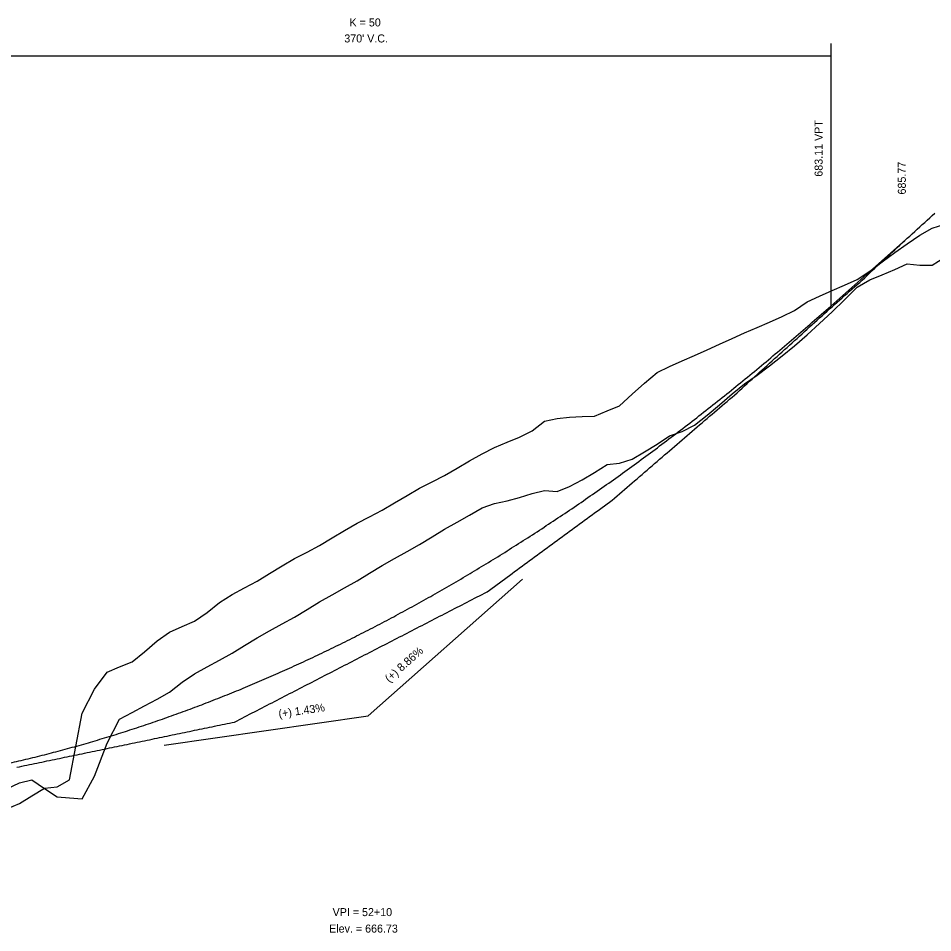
# Model space of a CAD drawing. Extents: x 1733584 to 1737559, y 1214897 to 1219897.
# Drawn here: x 1735549.8 to 1735915.5, y 1217977.4 to 1218342.9 of the extents above; entities that cross this region are included whole.
import ezdxf

# ---------------------------------------------------------------- set-up
doc = ezdxf.new("R2010")
doc.units = 0
for name, color, linetype in [('RD_DDB_GradeTX', 7, 'Continuous'), ('RD_DDB_Profile_EX', 7, 'Continuous'), ('RD_DDB_Profile_Lbl', 7, 'Continuous'), ('RD_DDB_Profile_PR', 7, 'Continuous'), ('RD_DDB_StripGrade', 7, 'Continuous'), ('RD_DDB_VCLbl', 7, 'Continuous'), ('RD_Sketch1', 7, 'Continuous'), ('RD_Sketch2', 7, 'Continuous')]:
    doc.layers.add(name, color=color, linetype=linetype)

msp = doc.modelspace()

# ---------------------------------------------------------------- linework, layer by layer
at = {"layer": 'RD_DDB_GradeTX'}
for p in [(1735751.45, 1218118.67), (1735608.21, 1218052.33)]:
    msp.add_line(p, (1735689.77, 1218064.03), dxfattribs=at)
at = {"layer": 'RD_DDB_Profile_EX'}
for points in [[(1735880.31, 1218232.06), (1735881.31, 1218232.95), (1735882.31, 1218233.83), (1735883.31, 1218234.72), (1735884.31, 1218235.6), (1735885.31, 1218236.49), (1735886.31, 1218237.37), (1735887.31, 1218238.27), (1735888.31, 1218239.22), (1735889.31, 1218240.17), (1735890.31, 1218241.12), (1735891.31, 1218242.07), (1735892.31, 1218243.02), (1735893.31, 1218243.94), (1735894.31, 1218244.87), (1735895.31, 1218245.79), (1735896.31, 1218246.71), (1735897.31, 1218247.63), (1735898.31, 1218248.55), (1735899.31, 1218249.47), (1735900.31, 1218250.39), (1735901.31, 1218251.31), (1735902.31, 1218252.22), (1735903.31, 1218253.14), (1735904.31, 1218254.05), (1735905.31, 1218254.97), (1735906.31, 1218255.88), (1735907.31, 1218256.79), (1735908.31, 1218257.71), (1735909.31, 1218258.62), (1735910.31, 1218259.53), (1735911.31, 1218260.44), (1735912.31, 1218261.35), (1735913.31, 1218262.29), (1735914.31, 1218263.22), (1735915.31, 1218264.15), (1735916.31, 1218265.09)], [(1735780.31, 1218145.17), (1735781.31, 1218145.9), (1735782.31, 1218146.62), (1735783.31, 1218147.35), (1735784.31, 1218148.08), (1735785.31, 1218148.81), (1735786.31, 1218149.53), (1735787.31, 1218150.26), (1735788.31, 1218151.09), (1735789.31, 1218151.97), (1735790.31, 1218152.84), (1735791.31, 1218153.71), (1735792.31, 1218154.58), (1735793.31, 1218155.44), (1735794.31, 1218156.3), (1735795.31, 1218157.17), (1735796.31, 1218158.03), (1735797.31, 1218158.89), (1735798.31, 1218159.76), (1735799.31, 1218160.62), (1735800.31, 1218161.48), (1735801.31, 1218162.34), (1735802.31, 1218163.2), (1735803.31, 1218164.06), (1735804.31, 1218164.92), (1735805.31, 1218165.79), (1735806.31, 1218166.65), (1735807.31, 1218167.5), (1735808.31, 1218168.36), (1735809.31, 1218169.22), (1735810.31, 1218170.08), (1735811.31, 1218170.94), (1735812.31, 1218171.8), (1735813.31, 1218172.66), (1735814.31, 1218173.53), (1735815.31, 1218174.4), (1735816.31, 1218175.26), (1735817.31, 1218176.13), (1735818.31, 1218176.98), (1735819.31, 1218177.84), (1735820.31, 1218178.7), (1735821.31, 1218179.55), (1735822.31, 1218180.4), (1735823.31, 1218181.26), (1735824.31, 1218182.11), (1735825.31, 1218182.97), (1735826.31, 1218183.82), (1735827.31, 1218184.67), (1735828.31, 1218185.52), (1735829.31, 1218186.37), (1735830.31, 1218187.23), (1735831.31, 1218188.08), (1735832.31, 1218188.93), (1735833.31, 1218189.78), (1735834.31, 1218190.63), (1735835.31, 1218191.48), (1735836.31, 1218192.32), (1735837.31, 1218193.19), (1735838.31, 1218194.12), (1735839.31, 1218195.05), (1735840.31, 1218195.97), (1735841.31, 1218196.9), (1735842.31, 1218197.82), (1735843.31, 1218198.73), (1735844.31, 1218199.63), (1735845.31, 1218200.54), (1735846.31, 1218201.45), (1735847.31, 1218202.35), (1735848.31, 1218203.26), (1735849.31, 1218204.16), (1735850.31, 1218205.07), (1735851.31, 1218205.97), (1735852.31, 1218206.87), (1735853.31, 1218207.78), (1735854.31, 1218208.68), (1735855.31, 1218209.58), (1735856.31, 1218210.48), (1735857.31, 1218211.38), (1735858.31, 1218212.28), (1735859.31, 1218213.18), (1735860.31, 1218214.08), (1735861.31, 1218214.98), (1735862.31, 1218215.89), (1735863.31, 1218216.8), (1735864.31, 1218217.72), (1735865.31, 1218218.64), (1735866.31, 1218219.55), (1735867.31, 1218220.47), (1735868.31, 1218221.37), (1735869.31, 1218222.27), (1735870.31, 1218223.16), (1735871.31, 1218224.05), (1735872.31, 1218224.95), (1735873.31, 1218225.84), (1735874.31, 1218226.73), (1735875.31, 1218227.62), (1735876.31, 1218228.51), (1735877.31, 1218229.4), (1735878.31, 1218230.29), (1735879.31, 1218231.17), (1735880.31, 1218232.06)], [(1735680.31, 1218084.28), (1735681.31, 1218084.8), (1735682.31, 1218085.31), (1735683.31, 1218085.83), (1735684.31, 1218086.34), (1735685.31, 1218086.86), (1735686.31, 1218087.37), (1735687.31, 1218087.89), (1735688.31, 1218088.41), (1735689.31, 1218088.92), (1735690.31, 1218089.44), (1735691.31, 1218089.95), (1735692.31, 1218090.47), (1735693.31, 1218090.98), (1735694.31, 1218091.5), (1735695.31, 1218092.01), (1735696.31, 1218092.53), (1735697.31, 1218093.04), (1735698.31, 1218093.56), (1735699.31, 1218094.07), (1735700.31, 1218094.59), (1735701.31, 1218095.1), (1735702.31, 1218095.62), (1735703.31, 1218096.13), (1735704.31, 1218096.65), (1735705.31, 1218097.16), (1735706.31, 1218097.68), (1735707.31, 1218098.19), (1735708.31, 1218098.71), (1735709.31, 1218099.22), (1735710.31, 1218099.74), (1735711.31, 1218100.26), (1735712.31, 1218100.78), (1735713.31, 1218101.29), (1735714.31, 1218101.81), (1735715.31, 1218102.32), (1735716.31, 1218102.84), (1735717.31, 1218103.35), (1735718.31, 1218103.87), (1735719.31, 1218104.38), (1735720.31, 1218104.9), (1735721.31, 1218105.41), (1735722.31, 1218105.93), (1735723.31, 1218106.45), (1735724.31, 1218106.96), (1735725.31, 1218107.48), (1735726.31, 1218107.99), (1735727.31, 1218108.51), (1735728.31, 1218109.02), (1735729.31, 1218109.54), (1735730.31, 1218110.05), (1735731.31, 1218110.57), (1735732.31, 1218111.08), (1735733.31, 1218111.6), (1735734.31, 1218112.11), (1735735.31, 1218112.63), (1735736.31, 1218113.14), (1735737.31, 1218113.66), (1735738.31, 1218114.36), (1735739.31, 1218115.1), (1735740.31, 1218115.83), (1735741.31, 1218116.57), (1735742.31, 1218117.31), (1735743.31, 1218118.04), (1735744.31, 1218118.78), (1735745.31, 1218119.52), (1735746.31, 1218120.25), (1735747.31, 1218120.99), (1735748.31, 1218121.72), (1735749.31, 1218122.46), (1735750.31, 1218123.19), (1735751.31, 1218123.93), (1735752.31, 1218124.66), (1735753.31, 1218125.4), (1735754.31, 1218126.13), (1735755.31, 1218126.87), (1735756.31, 1218127.6), (1735757.31, 1218128.33), (1735758.31, 1218129.07), (1735759.31, 1218129.8), (1735760.31, 1218130.53), (1735761.31, 1218131.27), (1735762.31, 1218132), (1735763.31, 1218132.74), (1735764.31, 1218133.47), (1735765.31, 1218134.21), (1735766.31, 1218134.95), (1735767.31, 1218135.68), (1735768.31, 1218136.41), (1735769.31, 1218137.14), (1735770.31, 1218137.87), (1735771.31, 1218138.6), (1735772.31, 1218139.33), (1735773.31, 1218140.06), (1735774.31, 1218140.79), (1735775.31, 1218141.52), (1735776.31, 1218142.25), (1735777.31, 1218142.98), (1735778.31, 1218143.71), (1735779.31, 1218144.44), (1735780.31, 1218145.17)], [(1735580.31, 1218049.99), (1735581.31, 1218050.2), (1735582.31, 1218050.41), (1735583.31, 1218050.62), (1735584.31, 1218050.82), (1735585.31, 1218051.03), (1735586.31, 1218051.24), (1735587.31, 1218051.45), (1735588.31, 1218051.66), (1735589.31, 1218051.86), (1735590.31, 1218052.07), (1735591.31, 1218052.28), (1735592.31, 1218052.49), (1735593.31, 1218052.69), (1735594.31, 1218052.9), (1735595.31, 1218053.11), (1735596.31, 1218053.32), (1735597.31, 1218053.52), (1735598.31, 1218053.73), (1735599.31, 1218053.94), (1735600.31, 1218054.15), (1735601.31, 1218054.35), (1735602.31, 1218054.56), (1735603.31, 1218054.77), (1735604.31, 1218054.98), (1735605.31, 1218055.18), (1735606.31, 1218055.39), (1735607.31, 1218055.6), (1735608.31, 1218055.81), (1735609.31, 1218056.01), (1735610.31, 1218056.22), (1735611.31, 1218056.43), (1735612.31, 1218056.63), (1735613.31, 1218056.85), (1735614.31, 1218057.05), (1735615.31, 1218057.26), (1735616.31, 1218057.47), (1735617.31, 1218057.67), (1735618.31, 1218057.88), (1735619.31, 1218058.09), (1735620.31, 1218058.3), (1735621.31, 1218058.5), (1735622.31, 1218058.71), (1735623.31, 1218058.92), (1735624.31, 1218059.13), (1735625.31, 1218059.33), (1735626.31, 1218059.54), (1735627.31, 1218059.75), (1735628.31, 1218059.95), (1735629.31, 1218060.16), (1735630.31, 1218060.37), (1735631.31, 1218060.58), (1735632.31, 1218060.78), (1735633.31, 1218060.99), (1735634.31, 1218061.2), (1735635.31, 1218061.4), (1735636.31, 1218061.62), (1735637.31, 1218062.14), (1735638.31, 1218062.65), (1735639.31, 1218063.17), (1735640.31, 1218063.68), (1735641.31, 1218064.2), (1735642.31, 1218064.71), (1735643.31, 1218065.23), (1735644.31, 1218065.74), (1735645.31, 1218066.26), (1735646.31, 1218066.77), (1735647.31, 1218067.29), (1735648.31, 1218067.8), (1735649.31, 1218068.32), (1735650.31, 1218068.83), (1735651.31, 1218069.35), (1735652.31, 1218069.86), (1735653.31, 1218070.38), (1735654.31, 1218070.89), (1735655.31, 1218071.41), (1735656.31, 1218071.92), (1735657.31, 1218072.43), (1735658.31, 1218072.95), (1735659.31, 1218073.46), (1735660.31, 1218073.98), (1735661.31, 1218074.5), (1735662.31, 1218075.01), (1735663.31, 1218075.53), (1735664.31, 1218076.04), (1735665.31, 1218076.56), (1735666.31, 1218077.07), (1735667.31, 1218077.59), (1735668.31, 1218078.1), (1735669.31, 1218078.62), (1735670.31, 1218079.13), (1735671.31, 1218079.65), (1735672.31, 1218080.16), (1735673.31, 1218080.68), (1735674.31, 1218081.19), (1735675.31, 1218081.71), (1735676.31, 1218082.22), (1735677.31, 1218082.74), (1735678.31, 1218083.25), (1735679.31, 1218083.77), (1735680.31, 1218084.28)], [(1735549.31, 1218043.55), (1735550.31, 1218043.76), (1735551.31, 1218043.97), (1735552.31, 1218044.18), (1735553.31, 1218044.38), (1735554.31, 1218044.59), (1735555.31, 1218044.8), (1735556.31, 1218045.01), (1735557.31, 1218045.21), (1735558.31, 1218045.42), (1735559.31, 1218045.63), (1735560.31, 1218045.84), (1735561.31, 1218046.04), (1735562.31, 1218046.26), (1735563.31, 1218046.47), (1735564.31, 1218046.67), (1735565.31, 1218046.88), (1735566.31, 1218047.09), (1735567.31, 1218047.3), (1735568.31, 1218047.5), (1735569.31, 1218047.71), (1735570.31, 1218047.92), (1735571.31, 1218048.13), (1735572.31, 1218048.33), (1735573.31, 1218048.54), (1735574.31, 1218048.75), (1735575.31, 1218048.96), (1735576.31, 1218049.16), (1735577.31, 1218049.37), (1735578.31, 1218049.58), (1735579.31, 1218049.79), (1735580.31, 1218049.99)]]:
    msp.add_lwpolyline(points, dxfattribs=at)
at = {"layer": 'RD_DDB_Profile_PR'}
msp.add_line((1735874.77, 1218227.9), (1735904.77, 1218254.48), dxfattribs=at)
msp.add_spline([(1735504.77, 1218037.5), (1735512.17, 1218038.62), (1735519.57, 1218039.85), (1735526.97, 1218041.18), (1735534.37, 1218042.63), (1735541.77, 1218044.18), (1735549.17, 1218045.85), (1735556.57, 1218047.62), (1735563.97, 1218049.51), (1735571.37, 1218051.5), (1735578.77, 1218053.61), (1735586.17, 1218055.82), (1735593.57, 1218058.15), (1735600.97, 1218060.58), (1735608.37, 1218063.13), (1735615.77, 1218065.78), (1735623.17, 1218068.54), (1735630.57, 1218071.42), (1735637.97, 1218074.4), (1735645.37, 1218077.5), (1735652.77, 1218080.7), (1735660.17, 1218084.01), (1735667.57, 1218087.44), (1735674.97, 1218090.97), (1735682.37, 1218094.61), (1735689.77, 1218098.37), (1735697.17, 1218102.23), (1735704.57, 1218106.2), (1735711.97, 1218110.29), (1735719.37, 1218114.48), (1735726.77, 1218118.78), (1735734.17, 1218123.19), (1735741.57, 1218127.71), (1735748.97, 1218132.35), (1735756.37, 1218137.09), (1735763.77, 1218141.94), (1735771.17, 1218146.9), (1735778.57, 1218151.97), (1735785.97, 1218157.16), (1735793.37, 1218162.45), (1735800.77, 1218167.85), (1735808.17, 1218173.36), (1735815.57, 1218178.98), (1735822.97, 1218184.71), (1735830.37, 1218190.55), (1735837.77, 1218196.5), (1735845.17, 1218202.56), (1735852.57, 1218208.73), (1735859.97, 1218215.01), (1735867.37, 1218221.4), (1735874.77, 1218227.9)], degree=3, dxfattribs=at)
at = {"layer": 'RD_DDB_VCLbl'}
for p, q in [((1735874.77, 1218332.9), (1735874.77, 1218227.9)), ((1735504.77, 1218327.9), (1735874.77, 1218327.9))]:
    msp.add_line(p, q, dxfattribs=at)
at = {"layer": 'RD_Sketch1'}
for points in [[(1735880.31, 1218230.4), (1735885.31, 1218235.43), (1735890.31, 1218238.44), (1735895.31, 1218240.38), (1735900.31, 1218242.51), (1735905.31, 1218244.83), (1735910.31, 1218244.22), (1735915.31, 1218244.29), (1735920.31, 1218247.48)], [(1735545.31, 1218034.91), (1735550.31, 1218037.29), (1735555.31, 1218038.51), (1735560.31, 1218035.08), (1735565.31, 1218031.74), (1735570.31, 1218031.36), (1735575.31, 1218030.97), (1735580.31, 1218039.96), (1735585.31, 1218053.18), (1735590.31, 1218062.76), (1735595.31, 1218065.43), (1735600.31, 1218068.1), (1735605.31, 1218070.78), (1735610.31, 1218073.52), (1735615.31, 1218077.53), (1735620.31, 1218080.84), (1735625.31, 1218083.61), (1735630.31, 1218086.37), (1735635.31, 1218089.13), (1735640.31, 1218092.23), (1735645.31, 1218095.25), (1735650.31, 1218098.02), (1735655.31, 1218100.8), (1735660.31, 1218103.57), (1735665.31, 1218106.64), (1735670.31, 1218109.69), (1735675.31, 1218112.47), (1735680.31, 1218115.25), (1735685.31, 1218118.03), (1735690.31, 1218121.11), (1735695.31, 1218124.2), (1735700.31, 1218126.98), (1735705.31, 1218129.77), (1735710.31, 1218132.55), (1735715.31, 1218135.65), (1735720.31, 1218138.77), (1735725.31, 1218141.57), (1735730.31, 1218144.36), (1735735.31, 1218147.17), (1735740.31, 1218148.96), (1735745.31, 1218150.01), (1735750.31, 1218151.33), (1735755.31, 1218152.91), (1735760.31, 1218154.18), (1735765.31, 1218153.72), (1735770.31, 1218155.75), (1735775.31, 1218158.46), (1735780.31, 1218161.4), (1735785.31, 1218164.59), (1735790.31, 1218165.08), (1735795.31, 1218166.66), (1735800.31, 1218169.56), (1735805.31, 1218172.68), (1735810.31, 1218176.02), (1735815.31, 1218177.74), (1735820.31, 1218180.29), (1735825.31, 1218184.27), (1735830.31, 1218188.44), (1735835.31, 1218192.8), (1735840.31, 1218196.76), (1735845.31, 1218200.33), (1735850.31, 1218204.04), (1735855.31, 1218207.95), (1735860.31, 1218212.04), (1735865.31, 1218216.34), (1735870.31, 1218220.9), (1735875.31, 1218225.56), (1735880.31, 1218230.4)]]:
    msp.add_lwpolyline(points, dxfattribs=at)
at = {"layer": 'RD_Sketch2'}
for points in [[(1735880.31, 1218236.29), (1735885.31, 1218238.52), (1735890.31, 1218241.81), (1735895.31, 1218245.53), (1735900.31, 1218249.25), (1735905.31, 1218252.82), (1735910.31, 1218256.23), (1735915.31, 1218259.09), (1735920.31, 1218260.61)], [(1735545.31, 1218026.91), (1735550.31, 1218029.04), (1735555.31, 1218032.12), (1735560.31, 1218035.2), (1735565.31, 1218035.73), (1735570.31, 1218038.52), (1735575.31, 1218065.2), (1735580.31, 1218074.74), (1735585.31, 1218081.58), (1735590.31, 1218083.64), (1735595.31, 1218085.69), (1735600.31, 1218089.72), (1735605.31, 1218094.1), (1735610.31, 1218097.59), (1735615.31, 1218099.74), (1735620.31, 1218101.9), (1735625.31, 1218105.33), (1735630.31, 1218109.45), (1735635.31, 1218112.63), (1735640.31, 1218115.26), (1735645.31, 1218117.92), (1735650.31, 1218120.97), (1735655.31, 1218124.02), (1735660.31, 1218126.96), (1735665.31, 1218129.56), (1735670.31, 1218132.16), (1735675.31, 1218135.18), (1735680.31, 1218138.21), (1735685.31, 1218141.13), (1735690.31, 1218143.7), (1735695.31, 1218146.28), (1735700.31, 1218149.2), (1735705.31, 1218152.23), (1735710.31, 1218155.12), (1735715.31, 1218157.66), (1735720.31, 1218160.21), (1735725.31, 1218163.03), (1735730.31, 1218166.05), (1735735.31, 1218168.87), (1735740.31, 1218171.34), (1735745.31, 1218173.53), (1735750.31, 1218175.47), (1735755.31, 1218178.01), (1735760.31, 1218181.88), (1735765.31, 1218182.96), (1735770.31, 1218183.49), (1735775.31, 1218183.8), (1735780.31, 1218183.9), (1735785.31, 1218186.07), (1735790.31, 1218188.06), (1735795.31, 1218192.63), (1735800.31, 1218197.03), (1735805.31, 1218201.27), (1735810.31, 1218203.68), (1735815.31, 1218205.97), (1735820.31, 1218208.19), (1735825.31, 1218210.43), (1735830.31, 1218212.69), (1735835.31, 1218214.95), (1735840.31, 1218217.15), (1735845.31, 1218219.32), (1735850.31, 1218221.51), (1735855.31, 1218223.7), (1735860.31, 1218226.18), (1735865.31, 1218229.57), (1735870.31, 1218231.82), (1735875.31, 1218234.06), (1735880.31, 1218236.29)]]:
    msp.add_lwpolyline(points, dxfattribs=at)

# ---------------------------------------------------------------- texts
at = {"layer": 'RD_DDB_GradeTX'}
for s, rotation, p in [('(+) 8.86%', 41.535, (1735698.15, 1218077.26)), ('(+) 1.43%', 8.1594, (1735654.12, 1218063.31))]:
    msp.add_text(s, height=3.2, rotation=rotation, dxfattribs=at).set_placement(p)
at = {"layer": 'RD_DDB_Profile_Lbl'}
msp.add_text('685.77', height=3.2, rotation=90, dxfattribs=at).set_placement((1735904.77, 1218272.48))
for s, p in [('VPI = 52+10', (1735675.52, 1217984.03)), ('Elev. = 666.73', (1735674.14, 1217977.44))]:
    msp.add_text(s, height=3.2, dxfattribs=at).set_placement(p)
at = {"layer": 'RD_DDB_StripGrade'}
msp.add_text('683.11 VPT', height=3.2, rotation=90, dxfattribs=at).set_placement((1735871.48, 1218279.61))
at = {"layer": 'RD_DDB_VCLbl'}
for s, p in [('K = 50', (1735682.29, 1218339.67)), ("370' V.C.", (1735680.21, 1218333.27))]:
    msp.add_text(s, height=3.2, dxfattribs=at).set_placement(p)

doc.saveas('drawing.dxf')
